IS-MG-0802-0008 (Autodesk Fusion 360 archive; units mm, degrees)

design "IS-MG-0802-0008" references "Digitus_DN-651107_LAN-Switch", "8 ports ethernet", "LED", "USB Type C Port (SMD Type) (1)", "3M Screw", "6 holes POWER", "DIP Switch", "2 SFP SLOT"
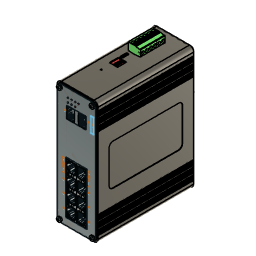
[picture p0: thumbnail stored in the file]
sketch "Sketch1" plane through (0, 0, 0) normal (0, 1, 0) x axis (1, 0, 0)
  line L1 (45, 0) -> (5, 0)
  line L2 (50, -145) -> (50, -5)
  line L3 (5, -150) -> (45, -150)
  line L4 (0, -5) -> (0, -145)
  arc A1 centre (5, -145) radius 5 clockwise from (5, -150) to (0, -145)
  arc A2 centre (45, -145) radius 5 clockwise from (50, -145) to (45, -150)
  arc A3 centre (5, -5) radius 5 clockwise from (0, -5) to (5, 0)
  arc A4 centre (45, -5) radius 5 clockwise from (45, 0) to (50, -5)
  point P1 (0, 0)
  point P2 (0, 0)
  point P4 (0, -150)
  point P3 (50, 0)
  horizontal L1
  vertical L2
  horizontal L3
  vertical L4
  coincident P1 P2
  coincident P4 L3
  coincident P4 L4
  tangent L3 A1
  tangent L4 A1
  tangent L2 A2
  tangent L3 A2
  equal A1 A2
  coincident P2 L1
  coincident P2 L4
  tangent L1 A3
  tangent L4 A3
  equal A1 A3
  coincident P3 L1
  coincident P3 L2
  tangent L1 A4
  tangent L2 A4
  equal A1 A4
  dimension "d1" distance P2 P3 = 50
  dimension "d2" distance P2 P4 = 150
  dimension "d3" radius A1 = 5
extrude "Extrude1" new body sketch "Sketch1" along normal blind 120
sketch "Sketch2" plane through (0, 0, 0) normal (0, -1, 0) x axis (1, 0, 0)
  line L1 (5, 150) -> (45, 150)
  line L2 (0, 5) -> (0, 145)
  line L3 (45, 0) -> (5, 0)
  line L4 (50, 145) -> (50, 5)
  line L5 (45, 1.5) -> (5, 1.5)
  line L6 (48.5, 145) -> (48.5, 5)
  line L7 (5, 148.5) -> (45, 148.5)
  line L8 (1.5, 5) -> (1.5, 145)
  line L9 (45, 0) -> (5, 0)
  line L10 (50, 145) -> (50, 5)
  line L11 (5, 150) -> (45, 150)
  line L12 (0, 5) -> (0, 145)
  arc A1 centre (45, 145) radius 5 clockwise from (45, 150) to (50, 145)
  arc A2 centre (5, 145) radius 5 clockwise from (0, 145) to (5, 150)
  arc A3 centre (5, 5) radius 5 clockwise from (5, 0) to (0, 5)
  arc A4 centre (45, 5) radius 5 clockwise from (50, 5) to (45, 0)
  arc A5 centre (45, 5) radius 3.5 clockwise from (48.5, 5) to (45, 1.5)
  arc A6 centre (45, 145) radius 3.5 clockwise from (45, 148.5) to (48.5, 145)
  arc A7 centre (5, 145) radius 3.5 clockwise from (1.5, 145) to (5, 148.5)
  arc A8 centre (5, 5) radius 3.5 clockwise from (5, 1.5) to (1.5, 5)
  arc A9 centre (45, 5) radius 5 clockwise from (50, 5) to (45, 0)
  arc A10 centre (45, 145) radius 5 clockwise from (45, 150) to (50, 145)
  arc A11 centre (5, 145) radius 5 clockwise from (0, 145) to (5, 150)
  arc A12 centre (5, 5) radius 5 clockwise from (5, 0) to (0, 5)
  dimension "d6" = -1.5
  dimension "d7" distance L3 = 0
extrude "Extrude2" cut sketch "Sketch2" against normal blind 1.5
sketch "Sketch3" plane through (0, 120, 0) normal (0, 1, 0) x axis (-1, 0, 0)
  line L1 (-50, 5) -> (-50, 145)
  line L2 (-5, 0) -> (-45, 0)
  line L3 (0, 145) -> (0, 5)
  line L4 (-45, 150) -> (-5, 150)
  line L5 (-5, 1.5) -> (-45, 1.5)
  line L6 (-1.5, 145) -> (-1.5, 5)
  line L7 (-45, 148.5) -> (-5, 148.5)
  line L8 (-48.5, 5) -> (-48.5, 145)
  line L9 (-5, 0) -> (-45, 0)
  line L10 (0, 145) -> (0, 5)
  line L11 (-45, 150) -> (-5, 150)
  line L12 (-50, 5) -> (-50, 145)
  arc A1 centre (-45, 145) radius 5 clockwise from (-50, 145) to (-45, 150)
  arc A2 centre (-45, 5) radius 5 clockwise from (-45, 0) to (-50, 5)
  arc A3 centre (-5, 5) radius 5 clockwise from (0, 5) to (-5, 0)
  arc A4 centre (-5, 145) radius 5 clockwise from (-5, 150) to (0, 145)
  arc A5 centre (-5, 5) radius 3.5 clockwise from (-1.5, 5) to (-5, 1.5)
  arc A6 centre (-5, 145) radius 3.5 clockwise from (-5, 148.5) to (-1.5, 145)
  arc A7 centre (-45, 145) radius 3.5 clockwise from (-48.5, 145) to (-45, 148.5)
  arc A8 centre (-45, 5) radius 3.5 clockwise from (-45, 1.5) to (-48.5, 5)
  arc A9 centre (-5, 5) radius 5 clockwise from (0, 5) to (-5, 0)
  arc A10 centre (-5, 145) radius 5 clockwise from (-5, 150) to (0, 145)
  arc A11 centre (-45, 145) radius 5 clockwise from (-50, 145) to (-45, 150)
  arc A12 centre (-45, 5) radius 5 clockwise from (-45, 0) to (-50, 5)
  dimension "d10" = -1.5
  dimension "d11" distance L2 = 0
extrude "Extrude3" cut sketch "Sketch3" against normal blind 1.5
sketch "Sketch4" plane through (0, 1.5, 0) normal (0, -1, 0) x axis (1, 0, 0)
  line L1 (1.5, 145) -> (1.5, 5)
  line L2 (45, 148.5) -> (5, 148.5)
  line L3 (48.5, 5) -> (48.5, 145)
  line L4 (5, 1.5) -> (45, 1.5)
  line L5 (45, 0) -> (5, 0)
  line L6 (50, 145) -> (50, 5)
  line L7 (5, 150) -> (45, 150)
  line L8 (0, 5) -> (0, 145)
  line L9 (25, 75) -> (25, 148.5)
  line L10 (25, 75) -> (1.5, 75)
  line L11 (0.75, 9) -> (0, 9)
  line L12 (0.75, 10.5) -> (0.75, 9)
  line L13 (0, 10.5) -> (0.75, 10.5)
  line L14 (0, 9) -> (0, 10.5)
  line L15 (0, 12.75) -> (0.75, 12.75)
  line L16 (0, 11.25) -> (0, 12.75)
  line L17 (0.75, 11.25) -> (0, 11.25)
  line L18 (0.75, 12.75) -> (0.75, 11.25)
  line L19 (0, 15) -> (0.75, 15)
  line L20 (0, 13.5) -> (0, 15)
  line L21 (0.75, 13.5) -> (0, 13.5)
  line L22 (0.75, 15) -> (0.75, 13.5)
  line L23 (0.75, 19.25) -> (0, 19.25)
  line L24 (0.75, 20.75) -> (0.75, 19.25)
  line L25 (0, 19.25) -> (0, 20.75)
  line L26 (0.75, 18.5) -> (0.75, 17)
  line L27 (0, 21.5) -> (0, 23)
  line L28 (0, 23) -> (0.75, 23)
  line L29 (0.75, 21.5) -> (0, 21.5)
  line L30 (0, 20.75) -> (0.75, 20.75)
  line L31 (0, 18.5) -> (0.75, 18.5)
  line L32 (0, 17) -> (0, 18.5)
  line L33 (0.75, 17) -> (0, 17)
  line L34 (0.75, 23) -> (0.75, 21.5)
  line L35 (0.75, 27.25) -> (0, 27.25)
  line L36 (0.75, 28.75) -> (0.75, 27.25)
  line L37 (0, 27.25) -> (0, 28.75)
  line L38 (0.75, 26.5) -> (0.75, 25)
  line L39 (0, 29.5) -> (0, 31)
  line L40 (0, 31) -> (0.75, 31)
  line L41 (0.75, 29.5) -> (0, 29.5)
  line L42 (0, 28.75) -> (0.75, 28.75)
  line L43 (0, 26.5) -> (0.75, 26.5)
  line L44 (0, 25) -> (0, 26.5)
  line L45 (0.75, 25) -> (0, 25)
  line L46 (0.75, 31) -> (0.75, 29.5)
  line L47 (0.75, 141) -> (0, 141)
  line L48 (0, 138.75) -> (0, 137.25)
  line L49 (0, 133) -> (0, 131.5)
  line L50 (0, 120.5) -> (0, 119)
  line L51 (0, 128.5) -> (0, 127)
  line L52 (0, 121.25) -> (0.75, 121.25)
  line L53 (0.75, 125) -> (0, 125)
  line L54 (0.75, 128.5) -> (0, 128.5)
  line L55 (0.75, 129.25) -> (0.75, 130.75)
  line L56 (0.75, 120.5) -> (0, 120.5)
  line L57 (0.75, 131.5) -> (0.75, 133)
  line L58 (0.75, 123.5) -> (0.75, 125)
  line L59 (0, 122.75) -> (0, 121.25)
  line L60 (0.75, 138.75) -> (0, 138.75)
  line L61 (0, 130.75) -> (0, 129.25)
  line L62 (0.75, 130.75) -> (0, 130.75)
  line L63 (0, 139.5) -> (0.75, 139.5)
  line L64 (0.75, 133) -> (0, 133)
  line L65 (0.75, 127) -> (0.75, 128.5)
  line L66 (0.75, 137.25) -> (0.75, 138.75)
  line L67 (0, 137.25) -> (0.75, 137.25)
  line L68 (0.75, 119) -> (0.75, 120.5)
  line L69 (0, 125) -> (0, 123.5)
  line L70 (0.75, 122.75) -> (0, 122.75)
  line L71 (0.75, 139.5) -> (0.75, 141)
  line L72 (0, 129.25) -> (0.75, 129.25)
  line L73 (0, 123.5) -> (0.75, 123.5)
  line L74 (0, 119) -> (0.75, 119)
  line L75 (0, 141) -> (0, 139.5)
  line L76 (0.75, 135) -> (0.75, 136.5)
  line L77 (0.75, 136.5) -> (0, 136.5)
  line L78 (0, 136.5) -> (0, 135)
  line L79 (0, 131.5) -> (0.75, 131.5)
  line L80 (0, 135) -> (0.75, 135)
  line L81 (0.75, 121.25) -> (0.75, 122.75)
  line L82 (0, 127) -> (0.75, 127)
  line L83 (49.25, 127) -> (49.25, 128.5)
  line L84 (50, 122.75) -> (50, 121.25)
  line L85 (49.25, 121.25) -> (49.25, 122.75)
  line L86 (50, 127) -> (49.25, 127)
  line L87 (49.25, 129.25) -> (49.25, 130.75)
  line L88 (49.25, 137.25) -> (49.25, 138.75)
  line L89 (50, 119) -> (49.25, 119)
  line L90 (50, 139.5) -> (49.25, 139.5)
  line L91 (50, 123.5) -> (49.25, 123.5)
  line L92 (50, 136.5) -> (50, 135)
  line L93 (50, 135) -> (49.25, 135)
  line L94 (50, 120.5) -> (50, 119)
  line L95 (50, 133) -> (50, 131.5)
  line L96 (49.25, 119) -> (49.25, 120.5)
  line L97 (50, 128.5) -> (50, 127)
  line L98 (49.25, 131.5) -> (49.25, 133)
  line L99 (49.25, 120.5) -> (50, 120.5)
  line L100 (49.25, 133) -> (50, 133)
  line L101 (50, 138.75) -> (50, 137.25)
  line L102 (50, 125) -> (50, 123.5)
  line L103 (49.25, 139.5) -> (49.25, 141)
  line L104 (49.25, 135) -> (49.25, 136.5)
  line L105 (49.25, 136.5) -> (50, 136.5)
  line L106 (50, 137.25) -> (49.25, 137.25)
  line L107 (49.25, 125) -> (50, 125)
  line L108 (50, 121.25) -> (49.25, 121.25)
  line L109 (49.25, 138.75) -> (50, 138.75)
  line L110 (50, 130.75) -> (50, 129.25)
  line L111 (49.25, 141) -> (50, 141)
  line L112 (49.25, 130.75) -> (50, 130.75)
  line L113 (50, 129.25) -> (49.25, 129.25)
  line L114 (50, 131.5) -> (49.25, 131.5)
  line L115 (49.25, 122.75) -> (50, 122.75)
  line L116 (50, 141) -> (50, 139.5)
  line L117 (49.25, 128.5) -> (50, 128.5)
  line L118 (49.25, 123.5) -> (49.25, 125)
  line L119 (50, 18.5) -> (49.25, 18.5)
  line L120 (49.25, 19.25) -> (50, 19.25)
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  point P22 (25, 148.5)
  point P23 (1.5, 75)
  point P25 (0, 9)
  point P74 (0, 141)
  point P26 (0.75, 9)
  point P81 (0.75, 141)
  point P27 (0.75, 10.5)
  point P77 (0.75, 139.5)
  point P28 (0, 10.5)
  point P69 (0, 139.5)
  point P29 (0.75, 12.75)
  point P67 (0.75, 137.25)
  point P30 (0, 12.75)
  point P68 (0, 137.25)
  point P31 (0, 11.25)
  point P89 (0, 138.75)
  point P32 (0.75, 11.25)
  point P86 (0.75, 138.75)
  point P33 (0.75, 15)
  point P79 (0.75, 135)
  point P34 (0, 15)
  point P94 (0, 135)
  point P35 (0, 13.5)
  point P90 (0, 136.5)
  point P36 (0.75, 13.5)
  point P65 (0.75, 136.5)
  point P37 (0.75, 17)
  point P95 (0.75, 133)
  point P38 (0, 19.25)
  point P96 (0, 130.75)
  point P39 (0.75, 19.25)
  point P75 (0.75, 130.75)
  point P40 (0.75, 20.75)
  point P72 (0.75, 129.25)
  point P41 (0.75, 23)
  point P73 (0.75, 127)
  point P42 (0, 20.75)
  point P62 (0, 129.25)
  point P43 (0, 23)
  point P61 (0, 127)
  point P44 (0.75, 18.5)
  point P63 (0.75, 131.5)
  point P45 (0, 21.5)
  point P66 (0, 128.5)
  point P46 (0, 17)
  point P70 (0, 133)
  point P47 (0.75, 21.5)
  point P91 (0.75, 128.5)
  point P48 (0, 18.5)
  point P84 (0, 131.5)
  point P49 (0.75, 25)
  point P83 (0.75, 125)
  point P50 (0, 27.25)
  point P76 (0, 122.75)
  point P51 (0.75, 27.25)
  point P78 (0.75, 122.75)
  point P52 (0.75, 28.75)
  point P88 (0.75, 121.25)
  point P53 (0.75, 31)
  point P87 (0.75, 119)
  point P54 (0, 28.75)
  point P82 (0, 121.25)
  point P55 (0, 31)
  point P80 (0, 119)
  point P56 (0.75, 26.5)
  point P85 (0.75, 123.5)
  point P57 (0, 29.5)
  point P93 (0, 120.5)
  point P58 (0, 25)
  point P92 (0, 125)
  point P59 (0.75, 29.5)
  point P71 (0.75, 120.5)
  point P60 (0, 26.5)
  point P64 (0, 123.5)
  point P5 (1.5, 145)
  point P123 (48.5, 145)
  point P21 (0, 145)
  point P106 (50, 145)
  point P145 (50, 9)
  point P140 (49.25, 9)
  point P158 (49.25, 10.5)
  point P153 (50, 10.5)
  point P166 (49.25, 12.75)
  point P170 (50, 12.75)
  point P169 (50, 11.25)
  point P167 (49.25, 11.25)
  point P151 (49.25, 15)
  point P152 (50, 15)
  point P154 (50, 13.5)
  point P161 (49.25, 13.5)
  point P143 (49.25, 17)
  point P141 (50, 19.25)
  point P137 (49.25, 19.25)
  point P160 (49.25, 20.75)
  point P155 (49.25, 23)
  point P156 (50, 20.75)
  point P162 (50, 23)
  point P159 (49.25, 18.5)
  point P148 (50, 21.5)
  point P149 (50, 17)
  point P147 (49.25, 21.5)
  point P165 (50, 18.5)
  point P168 (49.25, 25)
  point P150 (50, 27.25)
  point P157 (49.25, 27.25)
  point P163 (49.25, 28.75)
  point P164 (49.25, 31)
  point P144 (50, 28.75)
  point P136 (50, 31)
  point P146 (49.25, 26.5)
  point P139 (50, 29.5)
  point P142 (50, 25)
  point P138 (49.25, 29.5)
  point P135 (50, 26.5)
  point P97 (50, 127)
  point P100 (50, 129.25)
  point P98 (49.25, 131.5)
  point P99 (50, 123.5)
  point P105 (49.25, 136.5)
  point P114 (50, 128.5)
  point P103 (49.25, 137.25)
  point P102 (50, 137.25)
  point P101 (50, 139.5)
  point P110 (50, 133)
  point P115 (49.25, 120.5)
  point P111 (49.25, 129.25)
  point P112 (49.25, 127)
  point P104 (50, 141)
  point P113 (49.25, 130.75)
  point P132 (50, 122.75)
  point P109 (49.25, 139.5)
  point P131 (49.25, 122.75)
  point P108 (49.25, 135)
  point P134 (50, 119)
  point P117 (49.25, 141)
  point P133 (50, 121.25)
  point P130 (49.25, 125)
  point P124 (50, 131.5)
  point P125 (49.25, 123.5)
  point P121 (49.25, 138.75)
  point P127 (49.25, 119)
  point P128 (49.25, 121.25)
  point P118 (50, 138.75)
  point P120 (50, 136.5)
  point P122 (49.25, 128.5)
  point P119 (50, 125)
  point P116 (50, 120.5)
  point P126 (50, 135)
  point P107 (49.25, 133)
  point P129 (50, 130.75)
  midpoint L2 P22
  perpendicular L2 L9
  midpoint L1 P23
  perpendicular L9 L10
  horizontal L11
  vertical L12
  horizontal L13
  vertical L14
  coincident L8 P25
  symmetric L10 P25 P74
  symmetric L10 P26 P81
  symmetric L10 P27 P77
  symmetric L10 P28 P69
  symmetric L10 P29 P67
  symmetric L10 P30 P68
  symmetric L10 P31 P89
  symmetric L10 P32 P86
  symmetric L10 P33 P79
  symmetric L10 P34 P94
  symmetric L10 P35 P90
  symmetric L10 P36 P65
  symmetric L10 P37 P95
  symmetric L10 P38 P96
  symmetric L10 P39 P75
  symmetric L10 P40 P72
  symmetric L10 P41 P73
  symmetric L10 P42 P62
  symmetric L10 P43 P61
  symmetric L10 P44 P63
  symmetric L10 P45 P66
  symmetric L10 P46 P70
  symmetric L10 P47 P91
  symmetric L10 P48 P84
  symmetric L10 P49 P83
  symmetric L10 P50 P76
  symmetric L10 P51 P78
  symmetric L10 P52 P88
  symmetric L10 P53 P87
  symmetric L10 P54 P82
  symmetric L10 P55 P80
  symmetric L10 P56 P85
  symmetric L10 P57 P93
  symmetric L10 P58 P92
  symmetric L10 P59 P71
  symmetric L10 P60 P64
  symmetric P5 L9 P123
  symmetric P21 L9 P106
  symmetric L9 P25 P145
  symmetric L9 P26 P140
  symmetric L9 P27 P158
  symmetric L9 P28 P153
  symmetric L9 P29 P166
  symmetric L9 P30 P170
  symmetric L9 P31 P169
  symmetric L9 P32 P167
  symmetric L9 P33 P151
  symmetric L9 P34 P152
  symmetric L9 P35 P154
  symmetric L9 P36 P161
  symmetric L9 P37 P143
  symmetric L9 P38 P141
  symmetric L9 P39 P137
  symmetric L9 P40 P160
  symmetric L9 P41 P155
  symmetric L9 P42 P156
  symmetric L9 P43 P162
  symmetric L9 P44 P159
  symmetric L9 P45 P148
  symmetric L9 P46 P149
  symmetric L9 P47 P147
  symmetric L9 P48 P165
  symmetric L9 P49 P168
  symmetric L9 P50 P150
  symmetric L9 P51 P157
  symmetric L9 P52 P163
  symmetric L9 P53 P164
  symmetric L9 P54 P144
  symmetric L9 P55 P136
  symmetric L9 P56 P146
  symmetric L9 P57 P139
  symmetric L9 P58 P142
  symmetric L9 P59 P138
  symmetric L9 P60 P135
  symmetric L9 P61 P97
  symmetric L9 P62 P100
  symmetric L9 P63 P98
  symmetric L9 P64 P99
  symmetric L9 P65 P105
  symmetric L9 P66 P114
  symmetric L9 P67 P103
  symmetric L9 P68 P102
  symmetric L9 P69 P101
  symmetric L9 P70 P110
  symmetric L9 P71 P115
  symmetric L9 P72 P111
  symmetric L9 P73 P112
  symmetric L9 P74 P104
  symmetric L9 P75 P113
  symmetric L9 P76 P132
  symmetric L9 P77 P109
  symmetric L9 P78 P131
  symmetric L9 P79 P108
  symmetric L9 P80 P134
  symmetric L9 P81 P117
  symmetric L9 P82 P133
  symmetric L9 P83 P130
  symmetric L9 P84 P124
  symmetric L9 P85 P125
  symmetric L9 P86 P121
  symmetric L9 P87 P127
  symmetric L9 P88 P128
  symmetric L9 P89 P118
  symmetric L9 P90 P120
  symmetric L9 P91 P122
  symmetric L9 P92 P119
  symmetric L9 P93 P116
  symmetric L9 P94 P126
  symmetric L9 P95 P107
  symmetric L9 P96 P129
  dimension "d14" distance P25 P28 = 1.5
  dimension "d15" distance P27 P28 = 0.75
  dimension "d24" distance L10 L40 = 44
  dimension "d18" R-Pattern1-uDistance = 0
  dimension "d19" R-Pattern1-vDistance = 4.5
  dimension "d22" R-Pattern2-uDistance = 0
  dimension "d23" R-Pattern2-vDistance = 16
extrude "Extrude4" cut sketch "Sketch4" against normal blind 125
sketch "Sketch13" plane through (0, 0, 0) normal (0, -1, 0) x axis (1, 0, 0)
  line L1 (1.5, 5) -> (1.5, 145)
  line L2 (45, 1.5) -> (5, 1.5)
  line L3 (48.5, 145) -> (48.5, 5)
  line L4 (5, 148.5) -> (45, 148.5)
  line L5 (25, 75) -> (25, 148.5)
  line L6 (25, 75) -> (1.5, 75)
  line L7 (37.9, 10.2) -> (12.1, 10.2)
  line L8 (37.9, 74) -> (37.9, 10.2)
  line L9 (12.1, 74) -> (37.9, 74)
  line L10 (12.1, 10.2) -> (12.1, 74)
  line L11 (36.225, 115) -> (13.775, 115)
  line L12 (36.975, 128.75) -> (36.975, 115.75)
  line L13 (13.775, 129.5) -> (36.225, 129.5)
  line L14 (13.025, 115.75) -> (13.025, 128.75)
  arc A1 centre (5, 5) radius 3.5 clockwise from (5, 1.5) to (1.5, 5)
  arc A2 centre (45, 5) radius 3.5 clockwise from (48.5, 5) to (45, 1.5)
  arc A3 centre (45, 145) radius 3.5 clockwise from (45, 148.5) to (48.5, 145)
  arc A4 centre (5, 145) radius 3.5 clockwise from (1.5, 145) to (5, 148.5)
  arc A5 centre (13.775, 115.75) radius 0.75 clockwise from (13.775, 115) to (13.025, 115.75)
  arc A6 centre (36.225, 115.75) radius 0.75 clockwise from (36.975, 115.75) to (36.225, 115)
  arc A7 centre (36.225, 128.75) radius 0.75 clockwise from (36.225, 129.5) to (36.975, 128.75)
  arc A8 centre (13.775, 128.75) radius 0.75 clockwise from (13.025, 128.75) to (13.775, 129.5)
  circle C1 centre (14.525, 133) radius 0.75
  circle C2 centre (19.025, 133) radius 0.75
  circle C3 centre (23.525, 133) radius 0.75
  circle C4 centre (14.525, 138) radius 0.75
  circle C5 centre (19.025, 138) radius 0.75
  circle C6 centre (23.525, 138) radius 0.75
  circle C7 centre (27.525, 138) radius 0.75
  circle C8 centre (5, 145) radius 1.5
  circle C9 centre (45, 145) radius 1.5
  circle C10 centre (5, 5) radius 1.5
  circle C11 centre (45, 5) radius 1.5
  point P14 (25, 148.5)
  point P15 (1.5, 75)
  point P21 (13.025, 115)
  point P22 (36.975, 129.5)
  point P23 (13.025, 129.5)
  point P18 (37.9, 10.2)
  point P19 (37.9, 74)
  point P20 (12.1, 74)
  point P36 (14.525, 133)
  midpoint L4 P14
  perpendicular L4 L5
  midpoint L1 P15
  perpendicular L1 L6
  horizontal L7
  vertical L8
  horizontal L9
  vertical L10
  symmetric L5 L8 L10
  horizontal L11
  vertical L12
  horizontal L13
  vertical L14
  coincident P21 L11
  coincident P21 L14
  tangent L11 A5
  tangent L14 A5
  tangent L11 A6
  tangent L12 A6
  equal A5 A6
  coincident P22 L12
  coincident P22 L13
  tangent L12 A7
  tangent L13 A7
  equal A5 A7
  coincident P23 L13
  coincident P23 L14
  tangent L13 A8
  tangent L14 A8
  equal A5 A8
  symmetric L5 L12 L14
  concentric A4 C8
  dimension "d228" distance P18 P19 = 63.8
  dimension "d229" distance P19 P20 = 25.8
  dimension "d230" distance L6 L9 = 1
  dimension "d231" distance P22 P23 = 23.95
  dimension "d232" distance P21 P23 = 14.5
  dimension "d233" radius A5 = 0.75
  dimension "d234" distance L6 L11 = 40
  dimension "d235" diameter C1 = 1.5
  dimension "d236" distance L13 P36 = 3.5
  dimension "d237" distance L14 P36 = 1.5
  dimension "d250" diameter C8 = 3
  dimension "d240" R-Pattern1-uDistance = 9
  dimension "d241" R-Pattern1-vDistance = 0
  dimension "d244" R-Pattern2-uDistance = 0
  dimension "d245" R-Pattern2-vDistance = 5
  dimension "d248" R-Pattern3-uDistance = 4
  dimension "d249" R-Pattern3-vDistance = 0
  dimension "d253" R-Pattern4-uDistance = 40
  dimension "d254" R-Pattern4-vDistance = 0
  dimension "d257" R-Pattern5-uDistance = 0
  dimension "d258" R-Pattern5-vDistance = -140
extrude "Extrude8" cut sketch "Sketch13" profile of L5 L7 L8 L9 L10 L11 L12 L13 L14 A5 A6 A7 A8 C1 C2 C3 C4 C5 C6 C7 C8 C9 C10 C11 against normal blind 3
shell "Shell2" innerThickness 1
sketch "Sketch11" plane through (0, 0, 150) normal (0, 0, 1) x axis (-1, 0, 0)
  line L1 (-5, -118.5) -> (-45, -118.5)
  line L2 (-5, -1.5) -> (-5, -118.5)
  line L3 (-45, -1.5) -> (-5, -1.5)
  line L4 (-45, -118.5) -> (-45, -1.5)
  line L5 (-25, -60) -> (-25, -118.5)
  line L6 (-25, -60) -> (-5, -60)
  line L7 (-22, -105) -> (-13.4, -105)
  line L8 (-22, -75) -> (-22, -105)
  line L9 (-13.4, -75) -> (-22, -75)
  line L10 (-13.4, -105) -> (-13.4, -75)
  line L11 (-16.56, -72) -> (-15.85, -72)
  line L12 (-17.81, -64.31) -> (-17.81, -70.75)
  line L13 (-15.85, -63.06) -> (-16.56, -63.06)
  line L14 (-14.6, -70.75) -> (-14.6, -64.31)
  line L15 (-24.6, -61.81) -> (-14.6, -61.81)
  line L16 (-24.6, -50.81) -> (-24.6, -61.81)
  line L17 (-14.6, -50.81) -> (-24.6, -50.81)
  line L18 (-14.6, -61.81) -> (-14.6, -50.81)
  arc A1 centre (-15.85, -64.31) radius 1.25 clockwise from (-15.85, -63.06) to (-14.6, -64.31)
  arc A2 centre (-16.56, -64.31) radius 1.25 clockwise from (-17.81, -64.31) to (-16.56, -63.06)
  arc A3 centre (-16.56, -70.75) radius 1.25 clockwise from (-16.56, -72) to (-17.81, -70.75)
  arc A4 centre (-15.85, -70.75) radius 1.25 clockwise from (-14.6, -70.75) to (-15.85, -72)
  circle C1 centre (-17.1, -38.31) radius 0.875
  point P6 (-25, -118.5)
  point P7 (-5, -60)
  point P9 (-13.4, -105)
  point P12 (-13.4, -75)
  point P10 (-22, -105)
  point P25 (-14.6, -61.81)
  point P28 (-14.6, -50.81)
  point P27 (-24.6, -50.81)
  point P29 (-17.1, -38.31)
  midpoint L1 P6
  perpendicular L1 L5
  midpoint L2 P7
  perpendicular L2 L6
  horizontal L7
  vertical L8
  horizontal L9
  vertical L10
  horizontal L11
  vertical L12
  horizontal L13
  vertical L14
  tangent L13 A1
  tangent L14 A1
  tangent L12 A2
  tangent L13 A2
  equal A1 A2
  tangent L11 A3
  tangent L12 A3
  equal A1 A3
  tangent L11 A4
  tangent L14 A4
  equal A1 A4
  horizontal L15
  vertical L16
  horizontal L17
  vertical L18
  collinear L14 L18
  dimension "d181" distance P9 P12 = 30
  dimension "d182" distance P9 P10 = 8.6
  dimension "d183" distance L5 L8 = 3
  dimension "d184" distance L6 L9 = 15
  dimension "d259" distance L11 L13 = 8.94
  dimension "d260" distance L12 L14 = 3.21
  dimension "d261" radius A1 = 1.25
  dimension "d262" distance L9 L11 = 3
  dimension "d263" distance L10 L14 = 1.2
  dimension "d264" distance P25 P28 = 11
  dimension "d265" distance P27 P28 = 10
  dimension "d267" distance L13 L15 = 1.25
  dimension "d268" diameter C1 = 1.75
  dimension "d269" distance L17 P29 = 12.5
  dimension "d270" distance L18 P29 = 2.5
extrude "Extrude9" cut sketch "Sketch11" profile of L6 L7 L8 L9 L10 L11 L12 L13 L14 A1 A2 A3 A4 L15 L16 L17 L18 C1 against normal blind 5
component_insert "Component Insert1"
joint "Assemble5" alignAngle 0 alignOffsetX 0 alignOffsetY 0 alignOffsetZ 1.5
rectangular_pattern "00000000-0000-0000-0000-000000000000" uSpaceDistance 9 vSpaceDistance 0
rectangular_pattern "00000000-0000-0000-0000-000000000000" uSpaceDistance 5 vSpaceDistance 0
rectangular_pattern "00000000-0000-0000-0000-000000000000" uSpaceDistance 4 vSpaceDistance 0
component_insert "Component Insert4"
joint "Assemble6" alignAngle -90 alignOffsetX 0 alignOffsetY 0 alignOffsetZ 0
rectangular_pattern "00000000-0000-0000-0000-000000000000" uSpaceDistance 40 vSpaceDistance 0
rectangular_pattern "00000000-0000-0000-0000-000000000000" uSpaceDistance -140 vSpaceDistance 0
component_insert "Component Insert7"
position "Position2"
component_insert "Component Insert10"
decal "Decal1"
sketch "Sketch9" plane through (50, 0, 0) normal (1, 0, 0) x axis (0, 1, 0)
  line L1 (118.5, 31) -> (1.5, 31)
  line L2 (118.5, 119) -> (118.5, 31)
  line L3 (1.5, 119) -> (118.5, 119)
  line L4 (1.5, 31) -> (1.5, 119)
  line L5 (60, 75) -> (60, 119)
  line L6 (60, 75) -> (1.5, 75)
  line L7 (100, 100) -> (20, 100)
  line L8 (105, 55) -> (105, 95)
  line L9 (20, 50) -> (100, 50)
  line L10 (15, 95) -> (15, 55)
  arc A1 centre (20, 55) radius 5 clockwise from (20, 50) to (15, 55)
  arc A2 centre (100, 55) radius 5 clockwise from (105, 55) to (100, 50)
  arc A3 centre (100, 95) radius 5 clockwise from (100, 100) to (105, 95)
  arc A4 centre (20, 95) radius 5 clockwise from (15, 95) to (20, 100)
  point P6 (60, 119)
  point P7 (1.5, 75)
  point P11 (15, 50)
  point P10 (105, 50)
  point P9 (15, 100)
  midpoint L3 P6
  perpendicular L3 L5
  midpoint L4 P7
  perpendicular L4 L6
  horizontal L7
  vertical L8
  horizontal L9
  vertical L10
  symmetric L6 L7 L9
  coincident P11 L9
  coincident P11 L10
  tangent L9 A1
  tangent L10 A1
  coincident P10 L8
  coincident P10 L9
  tangent L8 A2
  tangent L9 A2
  equal A1 A2
  tangent L7 A3
  tangent L8 A3
  equal A1 A3
  coincident P9 L7
  coincident P9 L10
  tangent L7 A4
  tangent L10 A4
  equal A1 A4
  dimension "d137" distance P9 P11 = 50
  dimension "d138" distance P10 P11 = 90
  dimension "d139" radius A1 = 5
extrude "Extrude7" cut sketch "Sketch9" profile of L5 L6 L7 L8 L9 L10 A1 A2 A3 A4 against normal blind 0.5
component_insert "Component Insert13"
component_insert "Component Insert14"
position "Position6"
component_insert "Component Insert18"
component_insert "Component Insert19"
position "Position7"
sketch "Sketch15" plane through (0, 0, 0) normal (0, -1, 0) x axis (1, 0, 0)
  dimension "d291" = 2
  dimension "d292" = 2
  dimension "d293" = 1
  dimension "d294" = 2
  dimension "d295" = 2
  dimension "d296" = 2
  dimension "d297" = 2
  dimension "d298" = 2
  dimension "d299" = 2
  dimension "d300" = 2
  dimension "d301" = 2
  dimension "d302" = 2
  dimension "d303" = 2
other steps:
joint_origin "JointOrigin5"
joint_origin "JointOrigin6"

design "LED"
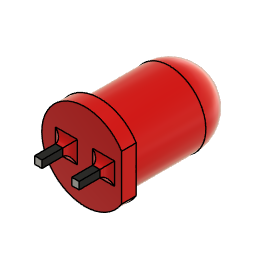
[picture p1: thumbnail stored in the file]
description: STEP AP214
part number: LED

design "8 ports ethernet"
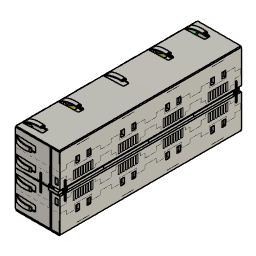
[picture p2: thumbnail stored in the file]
description: STEP AP214
part number: 8 ports ethernet

design "2 SFP SLOT"
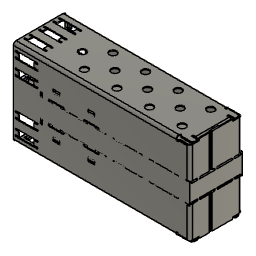
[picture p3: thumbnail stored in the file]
description: STEP AP214
part number: SFP SLOT

design "USB Type C Port (SMD Type) (1)"
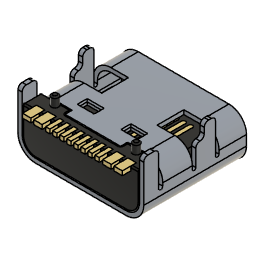
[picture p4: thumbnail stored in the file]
description: STEP AP214
part number: USB Type C Port (SMD Type) (1)

design "6 holes POWER"
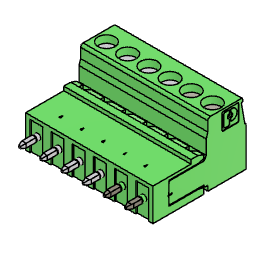
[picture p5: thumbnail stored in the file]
description: STEP AP214
part number: POWER

design "3M Screw"
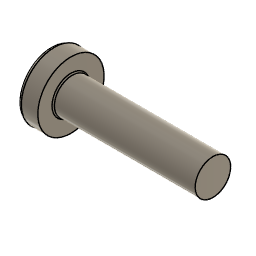
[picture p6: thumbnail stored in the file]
description: STEP AP214
part number: 3M Screw

design "DIP Switch"
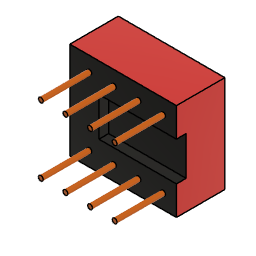
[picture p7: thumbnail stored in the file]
description: STEP AP214
part number: DIP Switch

design "Digitus_DN-651107_LAN-Switch"
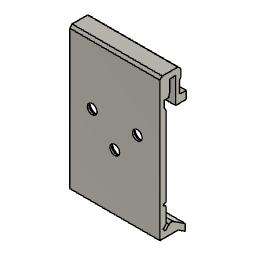
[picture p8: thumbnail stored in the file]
description: STEP AP214
part number: Digitus_DN-651107_LAN-Switch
